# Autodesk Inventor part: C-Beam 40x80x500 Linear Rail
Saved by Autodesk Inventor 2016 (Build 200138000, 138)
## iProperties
Created: 2016-03
Part Number: C-Beam 40x80x500 Linear Rail
Material: Generic
Document SubType Name: Modeling
Designer: bongo_000
Density: 1 g/cm^3
Appearance: Default
Author: bongo_000
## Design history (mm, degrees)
feature "BOSS-EXTRUDE1"
body "Solid1"
